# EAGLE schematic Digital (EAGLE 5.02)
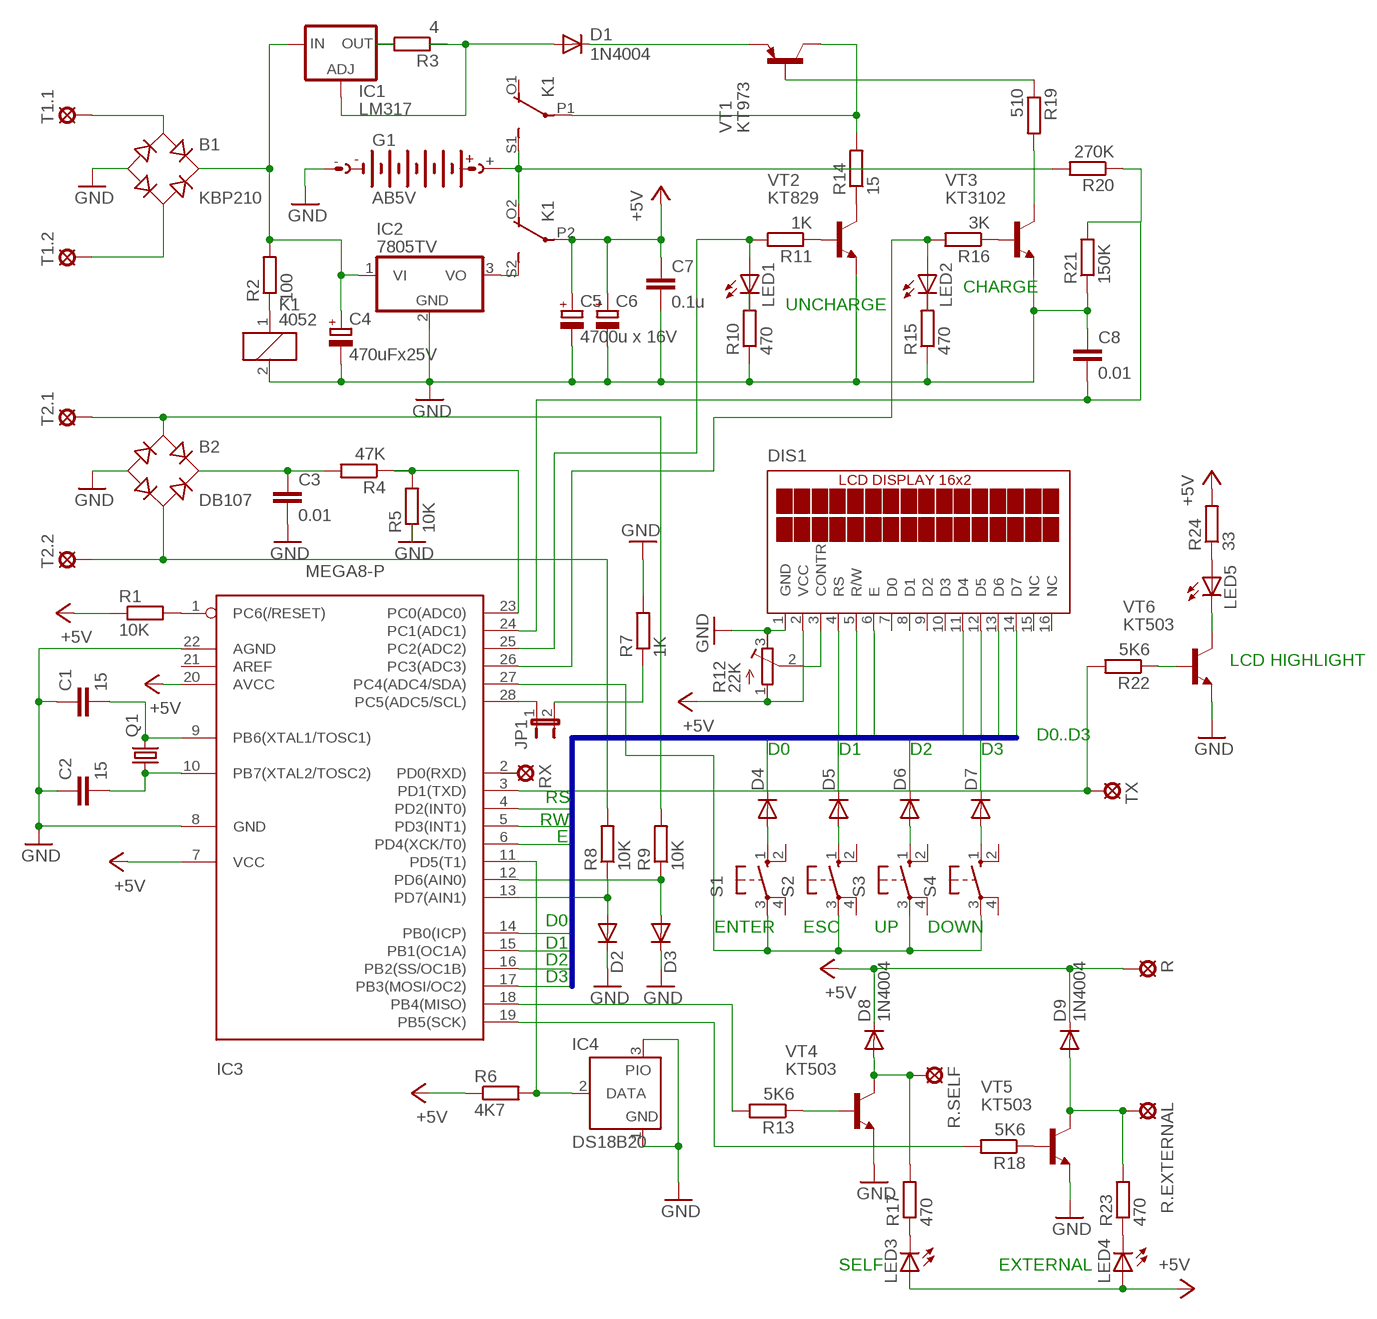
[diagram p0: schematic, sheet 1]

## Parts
B1  KBP210  RECTIFIER-2KBP  [2KBP]
B2  DB107  DBDB107G  [DB]
C1  15  C-EU025-025X050  [C025-025X050]
C2  15  C-EU025-025X050  [C025-025X050]
C3  0.01  C-EU050-025X075  [C050-025X075]
C4  470uFx25V  CPOL-EUE5-10.5  [E5-10,5]
C5  4700u x 16V  CPOL-EUE5-10.5  [E5-10,5]
C6  CPOL-EUE5-10.5  [E5-10,5]
C7  0.1u  C-EU050-025X075  [C050-025X075]
C8  0.01  C-EU050-025X075  [C050-025X075]
D1  1N4004  BAS15  [DO34-7]
D2  BAS15  [DO34-7]
D3  BAS15  [DO34-7]
D4  BAS15  [DO34-7]
D5  BAS15  [DO34-7]
D6  BAS15  [DO34-7]
D7  BAS15  [DO34-7]
D8  1N4004  [DO41-10]
D9  1N4004  [DO41-10]
DIS1  TUXGR_16X2_R2  [TUXGR_16X2_R2]
G1  AB5V  AB9V  [AB9V]
IC1  LM317  LM317TS  [317TS]
IC2  7805TV  [TO220V]
IC3  MEGA8-P  [DIL28-3]
IC4  DS18B20  DS2405  [TO92-]
JP1  JP1E  [JP1]
K1  4052  [F4052]
LED1  LED3MM  [LED3MM]
LED2  LED3MM  [LED3MM]
LED3  LED3MM  [LED3MM]
LED4  LED3MM  [LED3MM]
LED5  LED3MM  [LED3MM]
Q1  CRYSTALHC49S  [HC49/S]
R  LSP10  [LSP10]
R1  10K  R-EU_0204/5  [0204/5]
R2  100  R-EU_0207/15  [0207/15]
R3  4  R-EU_0204/5  [0204/5]
R4  47K  R-EU_0204/5  [0204/5]
R5  10K  R-EU_0204/5  [0204/5]
R6  4K7  R-EU_0204/5  [0204/5]
R7  1K  R-EU_0204/5  [0204/5]
R8  10K  R-EU_0204/5  [0204/5]
R9  10K  R-EU_0204/5  [0204/5]
R10  470  R-EU_0204/5  [0204/5]
R11  1K  R-EU_0204/5  [0204/5]
R12  22K  R-TRIMM3339P  [RTRIM3339P]
R13  5K6  R-EU_0204/5  [0204/5]
R14  15  R-EU_0414/5V  [0414V]
R15  470  R-EU_0204/5  [0204/5]
R16  3K  R-EU_0204/5  [0204/5]
R17  470  R-EU_0204/5  [0204/5]
R18  5K6  R-EU_0204/5  [0204/5]
R19  510  R-EU_0204/5  [0204/5]
R20  270K  R-EU_0204/5  [0204/5]
R21  150K  R-EU_0204/5  [0204/5]
R22  5K6  R-EU_0204/5  [0204/5]
R23  470  R-EU_0204/5  [0204/5]
R24  33  R-EU_0204/5  [0204/5]
R.EXTERNAL  LSP10  [LSP10]
R.SELF  LSP10  [LSP10]
RX  LSP10  [LSP10]
S1  10-XX  [B3F-10XX]
S2  10-XX  [B3F-10XX]
S3  10-XX  [B3F-10XX]
S4  10-XX  [B3F-10XX]
T1.1  T1.1  MCS10B  [MCS10B]
T1.2  MCS10B  [MCS10B]
T2.1  MCS10B  [MCS10B]
T2.2  MCS10B  [MCS10B]
TX  LSP10  [LSP10]
VT1  KT973  BD140  [TO126]
VT2  KT829  BD239  [TO220]
VT3  KT3102  2N4416  [TO92]
VT4  KT503  2N4416  [TO92]
VT5  KT503  2N4416  [TO92]
VT6  KT503  2N4416  [TO92]

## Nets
D0: D4.C DIS1.11(D4) IC3.14(PB0(ICP))
D1: D5.C DIS1.12(D5) IC3.15(PB1(OC1A))
D2: D6.C DIS1.13(D6) IC3.16(PB2(SS/OC1B))
D3: D7.C DIS1.14(D7) IC3.17(PB3(MOSI/OC2))
E: DIS1.6(E) IC3.6(PD4(XCK/T0))
N$1: D2.A IC3.13(PD7(AIN1)) R8.1
N$4: DIS1.3(CONTR) R12.2(S)
N$5: C1.2 IC3.9(PB6(XTAL1/TOSC1)) Q1.2
N$6: D4.A S1.1(S)
N$7: D5.A S2.1(S)
N$8: D6.A S3.1(S)
N$9: D7.A S4.1(S)
N$10: IC3.27(PC4(ADC4/SDA)) S1.3(P) S2.3(P) S3.3(P) S4.3(P)
N$11: B1.+ C4.+ IC1.3(IN) IC2.1(VI) R2.2
N$14: B1.AC2 T1.2.MP
N$15: B2.AC1 R9.2 T2.1.MP
N$16: B2.AC2 R8.2 T2.2.MP
N$18: R14.1 VT2.2(C)
N$19: IC3.1(PC6(/RESET)) R1.2
N$22: R11.1 VT2.1(B)
N$23: R16.1 VT3.2(B)
N$24: LED1.K(C) R10.2
N$25: R19.2 VT3.1(C)
N$27: B2.+ C3.1 R4.2
N$31: LED2.K(C) R15.2
N$32: IC3.26(PC3(ADC3)) LED2.A R16.2
N$33: R19.1 VT1.3(B)
N$34: IC1.2(OUT) R3.2
N$36: D1.C VT1.1(E)
N$37: IC3.23(PC0(ADC0)) R4.1 R5.2
N$40: D9.A R23.2 R.EXTERNAL.MP VT5.1(C)
N$41: D1.A IC1.1(ADJ) R3.1
N$43: JP1.2 R7.1
N$44: IC3.18(PB4(MISO)) R13.2
N$45: IC3.28(PC5(ADC5/SCL)) JP1.1
N$46: IC3.19(PB5(SCK)) R18.2
N$48: LED3.K(C) R17.1
N$49: LED4.K(C) R23.1
N$50: LED5.K(C) VT6.1(C)
N$51: LED5.A R24.1
N$52: IC3.2(PD0(RXD)) RX.MP
N$55: K1.1 R2.1
N$69: B1.AC1 T1.1.MP
N$87: IC2.3(VO) K1.S2(3:S)
N$100: D3.A IC3.12(PD6(AIN0)) R9.1
N$194: G1.+ K1.O2(3:O) K1.S1(2:S) R20.2
N$208: B1.- B2.- C1.1 C2.1 C3.2 C4.- C5.- C6.- C7.2 C8.1 D2.C D3.C DIS1.1(GND) G1.- IC2.2(GND) IC3.8(GND) IC3.22(AGND) IC4.1(GND) IC4.3(PIO) K1.2 R5.1 R7.2 R10.1 R12.3(A) R15.1 R21.1 VT2.3(E) VT3.3(E) VT4.3(E) VT5.3(E) VT6.3(E) ; supply symbol labelled GND
N$212: R22.1 VT6.2(B)
N$214: IC3.3(PD1(TXD)) R22.2 TX.MP
N$230: R13.1 VT4.2(B)
N$248: IC3.11(PD5(T1)) IC4.2(DATA) R6.2
N$253: R18.1 VT5.2(B)
N$254: D8.A R17.2 R.SELF.MP VT4.1(C)
N$263: K1.P1(2:P) R14.2 VT1.2(C)
N$290: C2.2 IC3.10(PB7(XTAL2/TOSC2)) Q1.1
N$293: C8.2 IC3.24(PC1(ADC1)) R20.1 R21.2
N$299: IC3.25(PC2(ADC2)) LED1.A R11.2
N$314: C5.+ C6.+ C7.1 D8.C D9.C DIS1.2(VCC) IC3.7(VCC) IC3.20(AVCC) K1.P2(3:P) LED3.A LED4.A R1.1 R6.1 R12.1(E) R24.2 R.MP ; supply symbol labelled +5V
RS: DIS1.4(RS) IC3.4(PD2(INT0))
RW: DIS1.5(R/W) IC3.5(PD3(INT1))
Unconnected: DIS1.7(D0) DIS1.8(D1) DIS1.9(D2) DIS1.10(D3) DIS1.15(NC) DIS1.16(NC) IC3.21(AREF) K1.O1(2:O) S1.2(S1) S1.4(P1) S2.2(S1) S2.4(P1) S3.2(S1) S3.4(P1) S4.2(S1) S4.4(P1)

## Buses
LED_BUS:D[0..3],RS,RW,E

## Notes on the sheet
- CHARGE
- UNCHARGE
- LCD HIGHLIGHT
- D0..D3
- D0 | D1 | D2 | D3
- RS
- RW
- E
- D0
- ENTER | ESC | UP | DOWN
- D1
- D2
- D3
- SELF | EXTERNAL

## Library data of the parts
B1 = rectifier:RECTIFIER-: Rectifier
B2 = rectifier:DB?*G: Single Phase 1.0 AMP Glass Passivated Bridge Rectifier Taiwan Semiconductor Co.,Ltd. - TSC Source: http://www.taiwansemi.com/TSCbig5/ezcatfiles/cust/img/img/db101g.pdf http://www.ts.com.tw/db/pictures/modules/PDT/PDT060207001/DBLS201G.pdf
C1-C3 C7 C8 = rcl:C-EU: CAPACITOR, European symbol
C4-C6 = rcl:CPOL-EU: POLARIZED CAPACITOR, European symbol
D1-D7 = diode:BAS15: DIODE
D8 D9 = diode:1N4004: DIODE
DIS1 = display-lcd:TUXGR_16X2_R2: Tuxgraphics LCD display 16x2 characters reflective, without background light Source: tuxgr_12x2_r2.pdf
G1 = battery:AB9V: 9-V BATTERY CLIP
IC1 = v-reg:LM317TS: VOLTAGE REGULATOR
IC2 = linear:78*: Positive VOLTAGE REGULATOR Source: http://cache.national.com/ds/LM/LM78L05.pdf http://www.fairchildsemi.com/ds/LM/LM7805.pdf
IC3 = atmel:MEGA8-P: MICROCONTROLLER 8 Kbytes FLASH, 1 kbytes SRAM, 512 bytes EEPROM, USART, 4-channel 10 bit ADC, 2-channel 8 bit ADC Pin compatible with Atmega48, ATMega88, ATMega168 Source: avr.lbr
IC4 = maxim:DS2405: Addressable Switch DALLAS Semiconductor
JP1 = jumper:JP1E: JUMPER
K1 = relay:4052: RELAY 2 x switch, Finder
LED1-LED5 = led:LED: LED
Q1 = crystal:CRYSTAL: CRYSTAL
R R.EXTERNAL R.SELF RX TX = solpad:LSP10: SOLDER PAD
R1 R3-R11 R13 R15-R24 = resistor:R-EU_: RESISTOR, European symbol
R2 R14 = rcl:R-EU_: RESISTOR, European symbol
R12 = rcl:R-TRIMM: Trimm resistor
S1-S4 = switch-omron:10-XX: OMRON SWITCH
T1.1 T1.2 T2.1 T2.2 = solpad:MCS10B: SOLDER PAD
VT1 = transistor-pnp:BD140: PNP Transistor
VT2 = transistor-npn:BD239*: NPN Transistor
VT3-VT6 = transistor-npn:2N4416: NPN Transistor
